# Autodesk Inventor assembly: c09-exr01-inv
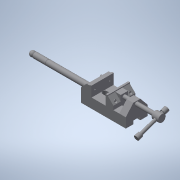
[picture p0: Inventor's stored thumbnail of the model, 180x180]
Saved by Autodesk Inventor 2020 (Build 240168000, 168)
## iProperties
Created: 2011-07
Part Number: c09-exr01-inv
Document SubType Name: Assembly
Designer: CadCim
Author: CadCim
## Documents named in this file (9)
- D:\Autodesk Inventor_2020\Resources\Resources\Inventor_2019_Exr\Inventor_2020_Exr\c09_inv_2020_exr\c09_Inv_exr_01\Drill Press Vice\Drill Press Vice Assembly.iam
- D:\Autodesk Inventor_2020\Resources\Resources\Inventor_2019_Exr\Inventor_2020_Exr\c09_inv_2020_exr\c09_Inv_exr_01\Drill Press Vice\Base.ipt
- D:\Autodesk Inventor_2020\Resources\Resources\Inventor_2019_Exr\Inventor_2020_Exr\c09_inv_2020_exr\c09_Inv_exr_01\Drill Press Vice\Jaw Face.ipt
- D:\Autodesk Inventor_2020\Resources\Resources\Inventor_2019_Exr\Inventor_2020_Exr\c09_inv_2020_exr\c09_Inv_exr_01\Drill Press Vice\Movable Jaw.ipt
- D:\Autodesk Inventor_2020\Resources\Resources\Inventor_2019_Exr\Inventor_2020_Exr\c09_inv_2020_exr\c09_Inv_exr_01\Drill Press Vice\Safety Handle.ipt
- D:\Autodesk Inventor_2020\Resources\Resources\Inventor_2019_Exr\Inventor_2020_Exr\c09_inv_2020_exr\c09_Inv_exr_01\Drill Press Vice\Clamp Screw.ipt
- D:\Autodesk Inventor_2020\Resources\Resources\Inventor_2019_Exr\Inventor_2020_Exr\c09_inv_2020_exr\c09_Inv_exr_01\Drill Press Vice\Clamp Screw Handle.ipt
- D:\Autodesk Inventor_2020\Resources\Resources\Inventor_2019_Exr\Inventor_2020_Exr\c09_inv_2020_exr\c09_Inv_exr_01\Drill Press Vice\Handle Stop.ipt
- D:\Autodesk Inventor_2020\Resources\Resources\Inventor_2019_Exr\Inventor_2020_Exr\c09_inv_2020_exr\c09_Inv_exr_01\Drill Press Vice\Cap Screw.ipt
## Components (13 placed, 8 different names)
1. Base:1 — Insert:3, Insert:9, Insert:10, Mate:8, Mate:9, Mate:12, Mate:13
2. Jaw Face:1 — Mate:10, Mate:11, Mate:12
3. Movable Jaw:1 — Mate:3, Insert:4, Insert:11, Insert:12, Mate:9, Mate:13, Mate:15
4. Safety Handle:1 — Insert:3
5. Clamp Screw:1 — Mate:3, Insert:4, Mate:4, Mate:6, Mate:8
6. Clamp Screw Handle:1 — Mate:4, Insert:7, Insert:8
7. Jaw Face:2 — Mate:14, Mate:15
8. Handle Stop:1 — Insert:7, Mate:6
9. Handle Stop:2 — Insert:8
10. Cap Screw:1 — Insert:12
11. Cap Screw:2 — Insert:11, Mate:14
12. Cap Screw:3 — Insert:10, Mate:11
13. Cap Screw:4 — Insert:9, Mate:10
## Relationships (19: Mate 11, Insert 8)
- Insert:3: Base:1 ↔ Safety Handle:1
- Mate:3: Movable Jaw:1 ↔ Clamp Screw:1
- Insert:4: Movable Jaw:1 ↔ Clamp Screw:1
- Mate:4: Clamp Screw:1 ↔ Clamp Screw Handle:1
- Insert:7: Clamp Screw Handle:1 ↔ Handle Stop:1
- Insert:8: Clamp Screw Handle:1 ↔ Handle Stop:2
- Mate:6: Clamp Screw:1 ↔ Handle Stop:1
- Insert:9: Base:1 ↔ Cap Screw:4
- Insert:10: Base:1 ↔ Cap Screw:3
- Insert:11: Movable Jaw:1 ↔ Cap Screw:2
- Insert:12: Movable Jaw:1 ↔ Cap Screw:1
- Mate:8: Base:1 ↔ Clamp Screw:1
- Mate:9: Base:1 ↔ Movable Jaw:1
- Mate:10: Jaw Face:1 ↔ Cap Screw:4
- Mate:11: Jaw Face:1 ↔ Cap Screw:3
- Mate:12: Base:1 ↔ Jaw Face:1
- Mate:13: Base:1 ↔ Movable Jaw:1
- Mate:14: Jaw Face:2 ↔ Cap Screw:2
- Mate:15: Movable Jaw:1 ↔ Jaw Face:2
